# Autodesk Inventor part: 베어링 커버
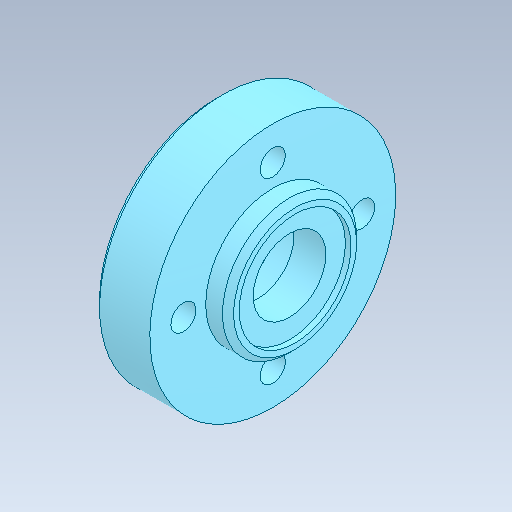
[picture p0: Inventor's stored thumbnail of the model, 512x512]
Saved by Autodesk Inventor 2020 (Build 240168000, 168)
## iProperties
Created: 2024-05
Part Number: 베어링 커버
Material: 강철, 연강
Document SubType Name: Modeling
Designer: oem
Density: 7.85 g/cm^3
Appearance: 기본값
Author: jhkim
Sending System: Autodesk Inventor 2025
Preprocessor: ST-DEVELOPER v20
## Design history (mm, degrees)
feature "솔리드1"
node "솔리드2"
